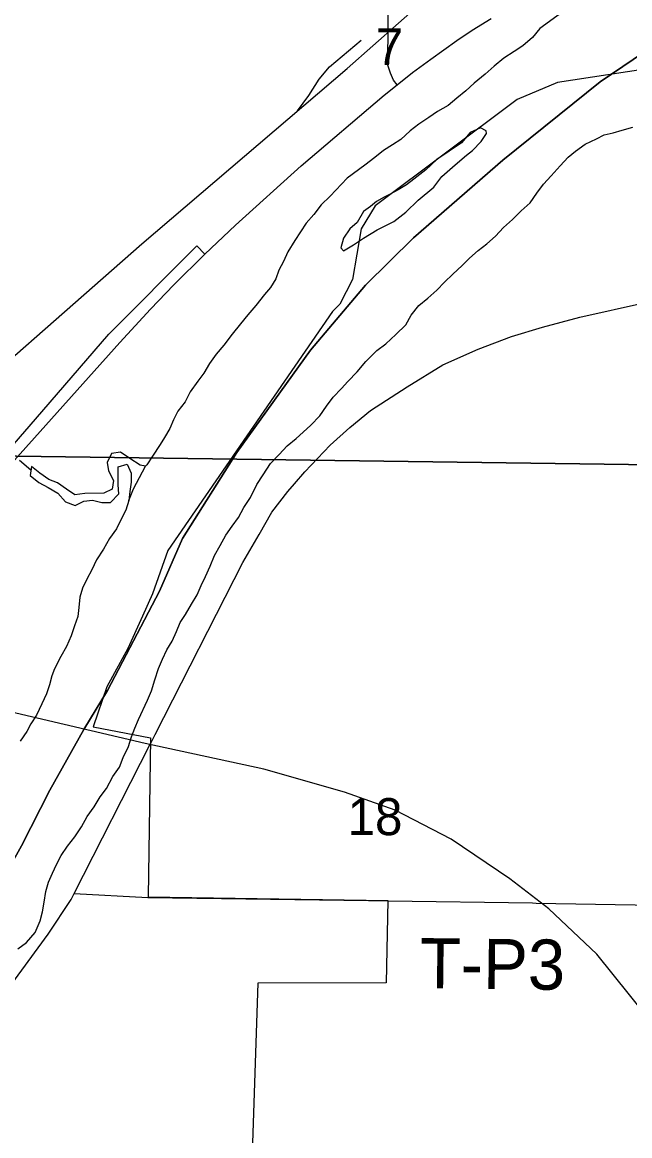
# Model space of a CAD drawing. Extents: x -6.2 to 37.4, y 0.2 to 22.2.
# Drawn here: x 2.958 to 3.302, y 17.002 to 17.632 of the extents above; entities that cross this region are included whole.
import ezdxf

# ---------------------------------------------------------------- set-up
doc = ezdxf.new("R2010")
doc.units = 0
for name, color, linetype in [('GM_X_City_Street', 7, 'Continuous'), ('GM_X_Corporation', 7, 'Continuous'), ('GM_X_County_Road', 7, 'Continuous'), ('GM_X_Major_River', 7, 'Continuous'), ('GM_X_Minor_River', 7, 'Continuous'), ('GM_X_Rail_Line', 7, 'Continuous'), ('GM_X_Section', 7, 'Continuous'), ('GM_X_Section_Text', 7, 'Continuous'), ('GM_X_State_Route', 7, 'Continuous'), ('GM_X_Township', 7, 'Continuous'), ('GM_X_Township_Road', 7, 'Continuous'), ('GM_X_Township_Road_Text', 7, 'Continuous')]:
    doc.layers.add(name, color=color, linetype=linetype)

msp = doc.modelspace()

# ---------------------------------------------------------------- linework, layer by layer
at = {"layer": 'GM_X_City_Street'}
msp.add_line((2.98735, 17.13923), (3.02906, 17.13706), dxfattribs=at)
for points in [[(3.17013, 17.59709), (3.16815, 17.59976), (3.16636, 17.60358), (3.16489, 17.60814), (3.16607, 17.74978)], [(2.8659, 17.28703), (2.85721, 17.29649), (2.8994, 17.33678), (2.9139, 17.3531), (2.93306, 17.37469), (2.94359, 17.38273), (2.96552, 17.4077), (3.00689, 17.45596), (3.0568, 17.50597), (3.06129, 17.50113)]]:
    msp.add_lwpolyline(points, dxfattribs=at)
at = {"layer": 'GM_X_Corporation'}
msp.add_lwpolyline([(3.3576, 17.61307), (3.26093, 17.59832), (3.23811, 17.58876), (3.15775, 17.52853), (3.14976, 17.51545), (3.14485, 17.48678), (3.13782, 17.47292), (3.13364, 17.46863), (3.0404, 17.33342), (3.03161, 17.30888), (3.02593, 17.29634), (3.01767, 17.27795), (3.00573, 17.25633), (2.99816, 17.23357), (3.0305, 17.22739), (3.02928, 17.13733), (3.16494, 17.13538), (3.16402, 17.08869), (3.0913, 17.08851), (3.0845, 16.88501)], dxfattribs=at)
at = {"layer": 'GM_X_County_Road'}
msp.add_lwpolyline([(2.95345, 17.38453), (3.0131, 17.45109), (3.03055, 17.47012), (3.04377, 17.48379), (3.06129, 17.50113), (3.0786, 17.51757), (3.11592, 17.55109), (3.16279, 17.59121), (3.17013, 17.59709), (3.17895, 17.60404), (3.18921, 17.61164), (3.20408, 17.62219), (3.21264, 17.62791), (3.22335, 17.6346)], dxfattribs=at)
at = {"layer": 'GM_X_Major_River'}
msp.add_line((3.15854, 17.5309), (3.15516, 17.52813), dxfattribs=at)
for points in [[(3.30279, 17.6619), (3.29806, 17.65956), (3.29288, 17.65625), (3.28791, 17.6535), (3.28197, 17.65002), (3.27678, 17.64633), (3.27122, 17.64283), (3.26622, 17.63914), (3.26143, 17.63639), (3.25644, 17.63289), (3.25106, 17.62901), (3.24678, 17.62379), (3.24139, 17.61915), (3.2364, 17.61584), (3.23064, 17.61216), (3.22506, 17.60753), (3.22007, 17.60303), (3.21381, 17.59803), (3.20906, 17.59362), (3.20405, 17.58955), (3.19904, 17.58529), (3.19311, 17.58199), (3.18811, 17.57849)], [(3.18811, 17.57849), (3.18255, 17.5748), (3.17754, 17.57092), (3.17227, 17.56602), (3.16754, 17.56315), (3.16255, 17.55984), (3.15755, 17.55595), (3.15197, 17.55151), (3.14197, 17.54413), (3.1323, 17.53408), (3.12727, 17.52906), (3.123, 17.52364), (3.11873, 17.51879), (3.11541, 17.51374), (3.11228, 17.50887), (3.10836, 17.5025), (3.10578, 17.49705), (3.10322, 17.49217), (3.10142, 17.48727), (3.09847, 17.48221), (3.09507, 17.47827), (3.09012, 17.47213), (3.08566, 17.46691), (3.08158, 17.46168), (3.07673, 17.4559), (3.07205, 17.44973), (3.06778, 17.4445), (3.06389, 17.43927), (3.0608, 17.4338), (3.05743, 17.42934), (3.05295, 17.42317), (3.05018, 17.41754), (3.0461, 17.41231), (3.04354, 17.40743), (3.04154, 17.40254), (3.03841, 17.39748), (3.03604, 17.39335), (3.03175, 17.3868), (3.02843, 17.38193), (3.02774, 17.38118)], [(3.06433, 17.32449), (3.06673, 17.33051), (3.07007, 17.33633), (3.07322, 17.34215), (3.07673, 17.3472), (3.08043, 17.35206), (3.08346, 17.35781), (3.0871, 17.36349), (3.09085, 17.37082), (3.09437, 17.37625), (3.09847, 17.38262), (3.10332, 17.38783), (3.10796, 17.39267), (3.11297, 17.39674), (3.11703, 17.40045), (3.12126, 17.40435), (3.12649, 17.40975), (3.13019, 17.41518), (3.1339, 17.42023), (3.13873, 17.42506), (3.14222, 17.42906), (3.1475, 17.43463), (3.15249, 17.44034), (3.15867, 17.44667), (3.16383, 17.45042), (3.16946, 17.45575), (3.17506, 17.46113), (3.1782, 17.46657), (3.18249, 17.47218), (3.18749, 17.47625), (3.19269, 17.48087), (3.19696, 17.48536), (3.20178, 17.48981), (3.20704, 17.49483), (3.21124, 17.49892), (3.21607, 17.50319), (3.22107, 17.50707), (3.22589, 17.51134), (3.23034, 17.51618), (3.23555, 17.52082), (3.24038, 17.52565), (3.24559, 17.53029), (3.2493, 17.53572), (3.25314, 17.54072), (3.25745, 17.54561), (3.26249, 17.5512), (3.26701, 17.55615), (3.27118, 17.55956), (3.27675, 17.56343), (3.28306, 17.56645), (3.28746, 17.56872), (3.2926, 17.56994), (3.29755, 17.57136), (3.30369, 17.57301)], [(3.15516, 17.52813), (3.15123, 17.52535), (3.14751, 17.51917), (3.14345, 17.51545), (3.13975, 17.51022), (3.13831, 17.50474), (3.13979, 17.50301), (3.14554, 17.5065), (3.1511, 17.51018), (3.15896, 17.51495), (3.16834, 17.5197), (3.17507, 17.52487), (3.18203, 17.53175), (3.19089, 17.53916), (3.19555, 17.54514), (3.20307, 17.55182), (3.20943, 17.55719), (3.21289, 17.55978), (3.21773, 17.56499), (3.22086, 17.56948), (3.2207, 17.571), (3.21733, 17.57278), (3.21159, 17.57005), (3.20655, 17.56427), (3.19964, 17.55947), (3.19272, 17.55468), (3.18636, 17.54893), (3.17962, 17.54356), (3.17558, 17.54042), (3.17079, 17.53767), (3.1662, 17.53511), (3.16276, 17.53347), (3.15854, 17.5309)], [(3.02774, 17.38118), (3.02478, 17.38175), (3.01886, 17.38554), (3.01363, 17.38906), (3.00851, 17.3884), (3.00594, 17.38333), (3.00679, 17.37857), (3.00951, 17.37301), (3.00884, 17.36809), (3.00406, 17.36591), (2.99346, 17.36575), (2.98776, 17.36491), (2.98291, 17.36823), (2.97788, 17.37175), (2.97299, 17.37356), (2.96796, 17.37726), (2.96312, 17.38096), (2.96244, 17.37585), (2.96728, 17.37196), (2.97252, 17.36901), (2.97813, 17.36586), (2.98238, 17.36104), (2.98783, 17.35884), (2.9928, 17.3614), (2.99773, 17.36187), (3.003, 17.36062), (3.00792, 17.36053), (3.01257, 17.36555), (3.0123, 17.37068), (3.01222, 17.37581), (3.01232, 17.38074), (3.01727, 17.38234), (3.01963, 17.37717), (3.01952, 17.37205), (3.01884, 17.36676), (3.01836, 17.36164)], [(3.01836, 17.36164), (3.02096, 17.36842), (3.02774, 17.38118)], [(3.01836, 17.36164), (3.01654, 17.35618), (3.01397, 17.35111), (3.01121, 17.34566), (3.00731, 17.34024), (3.00397, 17.33424), (3.00005, 17.32806), (2.99729, 17.32242), (2.99453, 17.31716), (2.99196, 17.31209), (2.99053, 17.307), (2.99003, 17.30113), (2.98935, 17.29602), (2.98754, 17.29074), (2.98572, 17.28509), (2.98294, 17.27908), (2.9798, 17.27345), (2.97612, 17.26651), (2.97465, 17.26255), (2.97341, 17.25745), (2.9716, 17.25236), (2.96902, 17.24654), (2.96592, 17.24023), (2.96283, 17.2353), (2.96055, 17.23096), (2.95684, 17.22553)], [(2.95534, 17.10795), (2.96033, 17.11145), (2.96518, 17.11724), (2.96816, 17.12382), (2.9694, 17.12891), (2.97027, 17.1344), (2.97134, 17.14045), (2.97278, 17.14573), (2.97497, 17.15081), (2.97734, 17.15569), (2.97991, 17.16076), (2.98361, 17.166), (2.9877, 17.17142), (2.99141, 17.17704), (2.99475, 17.18285), (2.99865, 17.18827), (3.00199, 17.1939), (3.00568, 17.19876), (3.00923, 17.20552), (3.01294, 17.21075), (3.01513, 17.21621), (3.0181, 17.22241), (3.01973, 17.22788), (3.02172, 17.23277), (3.02372, 17.23785), (3.02887, 17.24875), (3.03106, 17.25402), (3.03309, 17.26024), (3.03511, 17.26665), (3.0373, 17.27192), (3.03987, 17.27718), (3.04281, 17.28205), (3.0452, 17.2875), (3.04739, 17.29258), (3.05033, 17.29728), (3.05385, 17.30308), (3.05699, 17.30832), (3.05918, 17.31359), (3.06175, 17.31866), (3.06433, 17.32449)]]:
    msp.add_lwpolyline(points, dxfattribs=at)
at = {"layer": 'GM_X_Minor_River'}
msp.add_lwpolyline([(2.96283, 17.37882), (2.95637, 17.38432)], dxfattribs=at)
at = {"layer": 'GM_X_Rail_Line'}
for points in [[(1.68086, 16.70625), (1.76291, 16.75192), (2.22097, 17.00557), (2.46431, 17.13956), (2.55096, 17.18814), (2.74322, 17.29341), (2.78445, 17.31777), (2.81399, 17.33433), (2.83834, 17.3483), (2.85977, 17.36258), (2.89872, 17.39571), (3.02565, 17.50711), (3.14192, 17.60631), (3.24354, 17.69623), (3.29532, 17.73582), (3.33196, 17.76367), (3.37104, 17.79348), (3.41794, 17.82281), (3.45898, 17.84626), (3.52017, 17.87663)], [(3.11376, 17.58228), (3.12013, 17.59101), (3.12613, 17.60023), (3.13191, 17.60714), (3.14979, 17.62224)], [(4.51581, 15.49152), (4.34373, 15.71146), (4.15537, 15.96223), (3.94276, 16.24245), (3.76202, 16.4811), (3.72772, 16.52372), (3.54268, 16.76695), (3.33946, 17.03487), (3.2833, 17.10501), (3.25603, 17.13067), (3.23395, 17.14755), (3.20084, 17.16996), (3.16903, 17.18652), (3.14046, 17.19659), (3.09469, 17.20958), (3.02749, 17.22419), (2.92036, 17.2492), (2.78434, 17.28135), (2.75382, 17.28947), (2.74311, 17.29369)]]:
    msp.add_lwpolyline(points, dxfattribs=at)
at = {"layer": 'GM_X_Section'}
for points in [[(3.41696, 17.8606), (3.41225, 17.38056), (2.91294, 17.3873), (2.92261, 17.86953)], [(2.91294, 17.3873), (3.41225, 17.38056), (3.4002, 16.88095), (2.90397, 16.89028), (2.9126, 17.3784)]]:
    msp.add_lwpolyline(points, close=True, dxfattribs=at)
at = {"layer": 'GM_X_State_Route'}
for points in [[(3.11215, 17.37125), (3.11792, 17.37801), (3.13229, 17.39301), (3.14346, 17.40314), (3.15514, 17.41276), (3.17579, 17.42611), (3.19599, 17.43851), (3.21605, 17.4474), (3.23498, 17.45453), (3.25256, 17.45981), (3.27371, 17.46544), (3.3109, 17.47385)], [(3.03021, 17.2234), (3.03088, 17.22472), (3.03316, 17.22919), (3.08289, 17.32663), (3.09204, 17.34253), (3.0993, 17.35516), (3.1083, 17.36674), (3.11215, 17.37125)], [(2.93033, 17.06256), (2.95197, 17.08803), (2.97263, 17.11615), (2.98566, 17.13592), (2.98735, 17.13923), (3.03021, 17.2234)]]:
    msp.add_lwpolyline(points, dxfattribs=at)
at = {"layer": 'GM_X_Township'}
for points in [[(3.31666, 17.62007), (3.28508, 17.59881), (3.22997, 17.55435), (3.17947, 17.5104), (3.15222, 17.48363), (3.12118, 17.44688), (3.07941, 17.38888), (3.04867, 17.34024), (3.03562, 17.31049), (3.00624, 17.25417), (2.99272, 17.23206), (2.97346, 17.19773), (2.95747, 17.16618), (2.90688, 17.07588), (2.91357, 17.34065), (2.91378, 17.35338), (2.92047, 17.7536), (2.92175, 17.83006), (2.92181, 17.83359), (2.92189, 17.83809), (2.92238, 17.86748), (2.92464, 17.99264), (2.93048, 18.21437), (2.93287, 18.3702)], [(2.87203, 15.37415), (2.88287, 15.8796), (2.89299, 16.38385), (2.90519, 16.87971), (2.9053, 16.8908), (2.90604, 16.9274), (2.9062, 16.95681), (2.90667, 17.03851), (2.90688, 17.07588), (2.95747, 17.16618), (2.97346, 17.19773), (2.99272, 17.23206), (3.00624, 17.25417), (3.03562, 17.31049), (3.04867, 17.34024), (3.07941, 17.38888), (3.12118, 17.44688), (3.15222, 17.48363), (3.17947, 17.5104), (3.22997, 17.55435), (3.28508, 17.59881), (3.31666, 17.62007)]]:
    msp.add_lwpolyline(points, dxfattribs=at)
at = {"layer": 'GM_X_Township_Road'}
for p, q in [((3.02906, 17.13706), (3.15405, 17.13526)), ((3.24883, 17.13388), (3.40845, 17.13076))]:
    msp.add_line(p, q, dxfattribs=at)
msp.add_lwpolyline([(3.15405, 17.13526), (3.16505, 17.1351), (3.24683, 17.13392), (3.24883, 17.13388)], dxfattribs=at)

# ---------------------------------------------------------------- texts
at = {"layer": 'GM_X_Section_Text'}
for s, height, p in [('7', 0.02093, (3.15811, 17.60817)), ('18', 0.020928, (3.14207, 17.17229))]:
    msp.add_text(s, height=height, rotation=0.00001, dxfattribs=at).set_placement(p)
at = {"layer": 'GM_X_Township_Road_Text'}
msp.add_text('T-P3', height=0.028409, rotation=359.31571, dxfattribs=at).set_placement((3.18288, 17.08566))

doc.saveas('drawing.dxf')
